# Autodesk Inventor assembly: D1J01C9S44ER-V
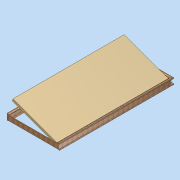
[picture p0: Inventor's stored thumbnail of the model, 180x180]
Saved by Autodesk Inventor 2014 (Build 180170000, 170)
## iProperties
Created: 2012-07
Part Number: D1J01C9S44ER-V
Document SubType Name: Assembly
Designer: david.appleford
Mass: 35000 g
Surface Area: 54366.8 cm^2
Volume: 91650.3 cm^3
Density: 0.381886 g/cm^3
Description: Door Frame 1 Width Style J01 RH
Cost Center: £369.00
Justset: False
Author: david.appleford
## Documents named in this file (3)
- C:\Documents and Settings\john.everitt\Local Settings\My Documents\Vault\Production MkII\VIRTUAL ELEMENTS\Virtual Doors\Star Projects\D1J01C9S44ER-V.iam
- C:\Documents and Settings\john.everitt\Local Settings\My Documents\Vault\Production MkII\Virtual Elements\Virtual Doors\Star Projects\D1J01C9S44-V.ipt
- C:\Documents and Settings\john.everitt\Local Settings\My Documents\Vault\Production MkII\VIRTUAL ELEMENTS\Virtual Doors\D44J01E-V.ipt
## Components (2 placed, 2 different names)
1. D1J01C9S44-V:1 — Mate:1, Mate:2, Mate:3, Angle:1
2. D44J01E-V:1 — Mate:1, Mate:2, Mate:3, Angle:1
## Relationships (4: Mate 3, Angle 1)
- Mate:1: D1J01C9S44-V:1 ↔ D44J01E-V:1
- Mate:2: D1J01C9S44-V:1 ↔ D44J01E-V:1
- Mate:3: D1J01C9S44-V:1 ↔ D44J01E-V:1
- Angle:1: D1J01C9S44-V:1 ↔ D44J01E-V:1
